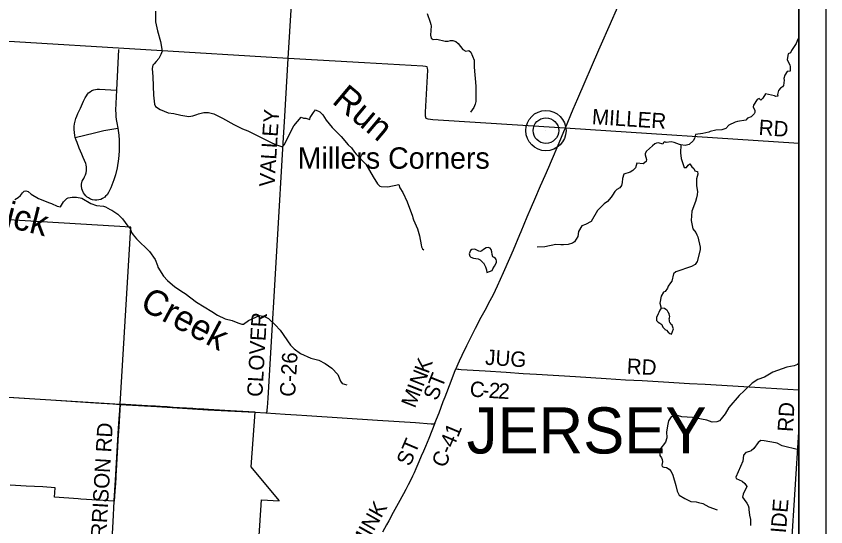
# Model space of a CAD drawing. Extents: x 0 to 91.3, y -0.7 to 22.
# Drawn here: x 6.008 to 9, y 18.226 to 20.113 of the extents above; entities that cross this region are included whole.
import ezdxf

# ---------------------------------------------------------------- set-up
doc = ezdxf.new("R2010")
doc.units = 0
for name, color, linetype in [('GM_X_Corporation', 7, 'Continuous'), ('GM_X_County_Road', 7, 'Continuous'), ('GM_X_County_Road_Text', 7, 'Continuous'), ('GM_X_Minor_Lake', 7, 'Continuous'), ('GM_X_Minor_River', 7, 'Continuous'), ('GM_X_Minor_River_Text', 7, 'Continuous'), ('GM_X_Township_Road', 7, 'Continuous'), ('GM_X_Township_Road_Text', 7, 'Continuous'), ('GM_X_Township_Text', 7, 'Continuous'), ('GM_X_Unincorporated', 7, 'Continuous'), ('GM_X_Unincorporated_Location', 7, 'Continuous'), ('GM_X_Unincorporated_Text', 7, 'Continuous'), ('SH_Data', 7, 'Continuous')]:
    doc.layers.add(name, color=color, linetype=linetype)

msp = doc.modelspace()

# ---------------------------------------------------------------- linework, layer by layer
at = {"layer": 'GM_X_Corporation'}
for points in [[(8.9, 14.1), (8.9, 20.9), (4.9555, 20.9), (4.9448, 20.7239), (4.9376, 20.6305), (4.9205, 20.3667), (4.8352, 18.7619), (4.834, 18.7568), (4.8336, 18.7529), (4.8277, 18.656), (4.8271, 18.6491), (4.8263, 18.646), (4.8251, 18.6439), (4.8242, 18.6326), (4.7833, 18.1361)], [(8.9, 15.2596), (8.9, 20.4953), (8.8785, 20.4965), (8.3956, 20.5276), (7.5521, 20.5793), (7.0477, 20.6033), (6.6637, 20.6293), (6.253, 20.6521), (5.6061, 20.6867), (4.9448, 20.7239), (4.9376, 20.6305), (4.9205, 20.3667), (4.8352, 18.7619), (4.834, 18.7568), (4.8336, 18.7529), (4.8277, 18.656), (4.8271, 18.6491), (4.8263, 18.646), (4.8251, 18.6439), (4.8242, 18.6326), (4.7833, 18.1361)], [(5.5451, 18.7322), (6.3918, 18.6787), (6.4311, 19.3332), (5.9167, 19.3643)], [(6.9007, 18.1177), (6.9141, 18.3252), (6.9792, 18.3213), (6.9793, 18.3233), (6.8762, 18.447), (6.8916, 18.6498), (6.7997, 18.6545), (6.7185, 18.6591), (6.6854, 18.6612), (6.6871, 18.6608), (6.6608, 18.6627), (6.6371, 18.6641), (6.636, 18.6642), (6.5876, 18.6671), (6.5653, 18.6685), (6.5405, 18.67), (6.5229, 18.6711), (6.4936, 18.6729), (6.4508, 18.6753), (6.3918, 18.6787), (6.3869, 18.5952), (6.384, 18.5468), (6.3822, 18.5174), (6.3812, 18.4997), (6.3785, 18.4551), (6.3761, 18.4138), (6.3757, 18.4077), (6.3744, 18.3859), (6.3727, 18.3576), (6.3705, 18.3205), (6.2473, 18.3276), (6.2373, 18.3287), (6.149, 18.3356), (6.1514, 18.3702), (6.1059, 18.3728), (6.045, 18.3762), (5.986, 18.3796)]]:
    msp.add_lwpolyline(points, dxfattribs=at)
at = {"layer": 'GM_X_County_Road'}
msp.add_line((6.8901, 18.6489), (6.93, 18.6467), dxfattribs=at)
for points in [[(6.93, 18.6467), (6.9336, 18.6494), (6.9353, 18.653), (6.936, 18.6574), (6.9365, 18.6665), (6.9388, 18.7016), (6.9771, 19.3495), (6.9908, 19.5807), (6.9947, 19.6438), (7.001, 19.743), (7.0134, 19.9559), (7.0324, 20.2772), (7.0426, 20.4438), (7.0492, 20.5571), (7.0503, 20.5744), (7.0503, 20.5854), (7.0499, 20.5936), (7.0491, 20.5984), (7.0479, 20.6028)], [(8.2333, 20.1542), (8.198, 20.0731), (8.1698, 20.009), (8.1602, 19.9873), (8.0825, 19.8073), (8.0656, 19.7677), (8.0368, 19.6987), (8.031, 19.6851), (8.0138, 19.6439), (7.9849, 19.5766), (7.975, 19.5536), (7.9615, 19.5234), (7.9448, 19.4851), (7.9229, 19.4348), (7.9111, 19.4066), (7.895, 19.3697), (7.8727, 19.3163), (7.8678, 19.3046), (7.8441, 19.2481), (7.8313, 19.2176), (7.8082, 19.1643), (7.7858, 19.1151), (7.7709, 19.0833), (7.7589, 19.0605), (7.7398, 19.025), (7.7255, 18.9987), (7.7042, 18.9582), (7.6912, 18.9336), (7.6718, 18.8944), (7.6545, 18.8587), (7.645, 18.8374), (7.6399, 18.8262), (7.6332, 18.8098)], [(7.5553, 18.6082), (7.5705, 18.6468), (7.5863, 18.6884), (7.5933, 18.7056), (7.6158, 18.7636), (7.628, 18.7971), (7.6332, 18.8098)], [(7.6332, 18.8098), (7.6403, 18.8083), (7.6437, 18.8079), (7.6526, 18.8072), (7.7415, 18.8018), (7.8187, 18.7968), (7.8814, 18.7928), (7.9313, 18.7898), (8.0749, 18.7817), (8.1888, 18.7738), (8.2592, 18.7694), (8.3207, 18.7658), (8.3998, 18.7613), (8.4963, 18.7559), (8.5542, 18.7525), (8.7373, 18.7412), (8.9, 18.7315)], [(5.5353, 18.731), (5.5363, 18.731), (5.5413, 18.7306), (5.6887, 18.7219), (5.882, 18.71), (5.98, 18.7044), (6.1355, 18.6949), (6.3006, 18.6844), (6.3651, 18.68), (6.3921, 18.6782)], [(6.3702, 18.3207), (6.3703, 18.3226), (6.3753, 18.3983), (6.3863, 18.5897), (6.3897, 18.6407), (6.3905, 18.6553), (6.3921, 18.6782)], [(6.3921, 18.6782), (6.5272, 18.6699), (6.7167, 18.6583), (6.8901, 18.6489)], [(6.93, 18.6467), (7.002, 18.6425), (7.0444, 18.6397), (7.0823, 18.6365), (7.3428, 18.6192), (7.4837, 18.6108), (7.5411, 18.6068), (7.545, 18.6062), (7.5486, 18.606), (7.5518, 18.6065), (7.5553, 18.6082)], [(7.5553, 18.6082), (7.533, 18.552), (7.5205, 18.5228), (7.5131, 18.5055), (7.5051, 18.4873), (7.496, 18.4662), (7.4848, 18.4401), (7.4781, 18.4254), (7.4725, 18.4133), (7.4648, 18.3964), (7.4567, 18.381), (7.4478, 18.364), (7.4393, 18.3481), (7.4192, 18.3114), (7.4011, 18.2784), (7.3847, 18.2477), (7.3765, 18.2324), (7.3618, 18.2063)], [(6.3746, 18.0328), (6.3737, 18.033), (6.3716, 18.0336), (6.3675, 18.0351), (6.3636, 18.0378), (6.3609, 18.0403), (6.3587, 18.0436), (6.3571, 18.0467), (6.3558, 18.0507), (6.3551, 18.055), (6.3547, 18.0604), (6.3553, 18.07), (6.3571, 18.0936), (6.3592, 18.1238), (6.3616, 18.17), (6.3636, 18.2011), (6.3664, 18.2435), (6.3702, 18.3207)]]:
    msp.add_lwpolyline(points, dxfattribs=at)
at = {"layer": 'GM_X_Minor_Lake'}
for points in [[(7.7244, 19.243), (7.718, 19.2438), (7.7028, 19.2514), (7.6922, 19.2511), (7.6869, 19.2474), (7.6822, 19.2349), (7.6845, 19.2258), (7.6882, 19.2219), (7.6977, 19.2185), (7.7151, 19.2165), (7.7231, 19.2119), (7.7336, 19.2016), (7.7355, 19.2008), (7.7419, 19.1867), (7.746, 19.175), (7.7456, 19.1742)], [(7.7456, 19.1742), (7.7478, 19.1651), (7.7664, 19.1729), (7.7699, 19.1786), (7.776, 19.1888), (7.7825, 19.202), (7.7829, 19.2085), (7.7818, 19.2134), (7.7796, 19.2172), (7.7743, 19.2207), (7.7694, 19.223), (7.7668, 19.2317), (7.7661, 19.242), (7.7635, 19.2503), (7.7597, 19.2549), (7.7525, 19.2583), (7.7445, 19.2561), (7.735, 19.2501), (7.7293, 19.2456), (7.7244, 19.243)], [(8.392, 19.0339), (8.3862, 19.0259), (8.3835, 19.0172), (8.3805, 19.0123), (8.3747, 18.9998), (8.3743, 18.9877), (8.3799, 18.9816), (8.3871, 18.9778), (8.3943, 18.9739), (8.3954, 18.9701), (8.3976, 18.9629), (8.4052, 18.9564), (8.4055, 18.9545), (8.4112, 18.9522), (8.418, 18.9446), (8.4237, 18.94), (8.4297, 18.9373)], [(8.4297, 18.9373), (8.4374, 18.9574), (8.4344, 18.9635), (8.4318, 18.9707), (8.4276, 18.9745), (8.4258, 18.9783), (8.4239, 18.9806), (8.4228, 18.9855), (8.422, 18.9889), (8.4213, 18.9939), (8.4221, 18.9984), (8.4232, 19.0026), (8.4225, 19.0052), (8.4207, 19.014), (8.4173, 19.0189), (8.4154, 19.0235), (8.412, 19.0269), (8.4082, 19.0292), (8.4037, 19.0319), (8.392, 19.0339)]]:
    msp.add_lwpolyline(points, dxfattribs=at)
at = {"layer": 'GM_X_Minor_River'}
for points in [[(6.523, 20.1312), (6.5228, 20.0918), (6.5302, 20.0584), (6.5413, 20.0193), (6.5479, 19.9836), (6.5429, 19.9707), (6.5345, 19.9567), (6.5257, 19.9458), (6.5181, 19.9371), (6.5132, 19.9318), (6.5101, 19.9193), (6.5129, 19.8882), (6.5148, 19.8207), (6.5192, 19.7881), (6.5233, 19.779), (6.5395, 19.7675), (6.569, 19.756), (6.5906, 19.7532), (6.6168, 19.747), (6.6459, 19.7426), (6.6611, 19.7444), (6.6759, 19.75), (6.682, 19.7523), (6.701, 19.7567), (6.718, 19.7574), (6.7385, 19.7523), (6.7702, 19.7362), (6.8126, 19.7124), (6.8443, 19.6967), (6.8636, 19.6894), (6.8833, 19.6787), (6.9472, 19.6468), (6.9661, 19.6387), (6.9918, 19.6302), (6.9983, 19.637), (7.0343, 19.7073), (7.0614, 19.7398), (7.0697, 19.7359), (7.0785, 19.7359), (7.0925, 19.7316), (7.0948, 19.7384), (7.1063, 19.7566), (7.1146, 19.7664), (7.1298, 19.7598), (7.1411, 19.7484), (7.1535, 19.729), (7.1757, 19.7016), (7.2085, 19.668), (7.2345, 19.6371), (7.2469, 19.6257), (7.2586, 19.6101), (7.2642, 19.6032), (7.2997, 19.5659), (7.3271, 19.5191), (7.3429, 19.4932), (7.3519, 19.4844), (7.3568, 19.4829), (7.3811, 19.4827), (7.4217, 19.4904), (7.4262, 19.4779), (7.4371, 19.4608), (7.4532, 19.4262), (7.4722, 19.3737), (7.4741, 19.3673), (7.4759, 19.3597), (7.4905, 19.327), (7.4987, 19.3016), (7.5042, 19.2678), (7.5057, 19.2598), (7.5095, 19.253), (7.5144, 19.2499)], [(7.5265, 20.1226), (7.5377, 20.0903), (7.5399, 20.0823), (7.5414, 20.0766), (7.5393, 20.0425), (7.5415, 20.0311), (7.5494, 20.0269), (7.5627, 20.0283), (7.593, 20.0202), (7.6044, 20.0209), (7.6127, 20.0231), (7.6211, 20.0231), (7.6324, 20.0196), (7.6415, 20.0123), (7.6584, 19.9902), (7.6698, 19.9837), (7.6808, 19.9856), (7.6875, 19.9794), (7.7003, 19.9498), (7.7006, 19.9437), (7.7001, 19.924), (7.7066, 19.8546), (7.7062, 19.7974), (7.7047, 19.7879), (7.6993, 19.775), (7.6867, 19.7584)], [(8.9, 20.032), (8.8968, 20.0283), (8.8941, 20.0219), (8.8899, 20.0117), (8.8731, 19.9864), (8.8696, 19.9773), (8.8609, 19.9732), (8.8577, 19.9523), (8.8675, 19.9314), (8.8686, 19.9265), (8.8681, 19.9098), (8.8567, 19.9087), (8.8491, 19.8948), (8.8448, 19.883), (8.8463, 19.8762), (8.8432, 19.8561), (8.8401, 19.8512), (8.8329, 19.8471), (8.8253, 19.8388), (8.8214, 19.8236), (8.8221, 19.8172), (8.8153, 19.8157), (8.8104, 19.8184), (8.7767, 19.8258), (8.7667, 19.81), (8.7598, 19.8024), (8.7531, 19.8081), (8.7466, 19.8055), (8.7328, 19.7836), (8.7313, 19.7783), (8.738, 19.7642), (8.7376, 19.757), (8.7349, 19.7518), (8.7242, 19.7408), (8.7106, 19.736), (8.7045, 19.7288), (8.6733, 19.7237), (8.6654, 19.7215), (8.6418, 19.7095), (8.6307, 19.6974), (8.6155, 19.6933), (8.5932, 19.692)], [(8.5932, 19.692), (8.573, 19.6871), (8.5677, 19.6845), (8.5461, 19.6793), (8.5184, 19.6761), (8.5149, 19.6613), (8.5099, 19.6519), (8.4951, 19.6387), (8.4799, 19.6346), (8.4647, 19.6374), (8.4594, 19.6382), (8.4401, 19.6462), (8.4284, 19.6482), (8.4106, 19.6457), (8.4053, 19.648), (8.4003, 19.6465), (8.398, 19.64), (8.3817, 19.6443), (8.3745, 19.6432), (8.3677, 19.6406), (8.3589, 19.6342), (8.3368, 19.6135), (8.3326, 19.6056), (8.3322, 19.5999), (8.3378, 19.5835), (8.3362, 19.576), (8.3244, 19.5673), (8.3013, 19.5694), (8.2963, 19.5523), (8.2868, 19.5429), (8.2769, 19.5358), (8.2541, 19.5294), (8.2483, 19.5124), (8.2478, 19.4984), (8.2444, 19.487), (8.2386, 19.4784), (8.2272, 19.4724), (8.22, 19.4652), (8.2112, 19.4512), (8.2066, 19.444), (8.1936, 19.4282), (8.1814, 19.4192), (8.1559, 19.3947), (8.1325, 19.3543), (8.1124, 19.343), (8.0987, 19.3382), (8.0865, 19.3174), (8.0833, 19.2981), (8.0715, 19.2788), (8.0639, 19.2743), (8.0483, 19.2691), (8.0308, 19.268), (8.021, 19.2681), (8.0024, 19.2694), (7.9614, 19.2609), (7.933, 19.2592)], [(8.4638, 19.6375), (8.463, 19.6078), (8.4656, 19.5866), (8.476, 19.5535), (8.4855, 19.5538), (8.4912, 19.5621), (8.4973, 19.5667), (8.5044, 19.5556), (8.5124, 19.5495), (8.5161, 19.5415), (8.5263, 19.5384), (8.5274, 19.5293), (8.5216, 19.5119), (8.5227, 19.496), (8.5215, 19.4861), (8.5252, 19.4645), (8.5243, 19.4524), (8.5216, 19.4418), (8.5185, 19.4278), (8.5051, 19.3926), (8.5022, 19.3581), (8.5088, 19.3266), (8.5198, 19.3136), (8.5231, 19.3053), (8.5273, 19.2973), (8.5354, 19.2597), (8.5357, 19.2495), (8.5249, 19.2056), (8.5172, 19.1954), (8.5035, 19.1875), (8.4462, 19.1681), (8.4374, 19.161), (8.4308, 19.133), (8.4255, 19.1277), (8.4174, 19.1152), (8.4151, 19.108), (8.4063, 19.0956), (8.4002, 19.0929), (8.3911, 19.0782), (8.3871, 19.0527), (8.392, 19.0339)], [(6.0031, 19.4356), (6.0153, 19.4431), (6.0244, 19.4502), (6.0317, 19.4604), (6.0378, 19.4657), (6.0439, 19.4679), (6.0518, 19.4648), (6.0635, 19.4549), (6.0907, 19.4388), (6.1312, 19.423), (6.138, 19.42), (6.1596, 19.4104), (6.1721, 19.4088), (6.1831, 19.4262), (6.195, 19.439), (6.1999, 19.4416), (6.2143, 19.4442), (6.2303, 19.4441), (6.2507, 19.4398), (6.284, 19.421), (6.3044, 19.4133), (6.3305, 19.4109), (6.3377, 19.4086), (6.3555, 19.399), (6.3612, 19.3955), (6.3831, 19.3817), (6.4012, 19.3638), (6.42, 19.3372), (6.429, 19.3276), (6.4339, 19.3128), (6.4399, 19.3052), (6.4519, 19.2896), (6.5006, 19.2427), (6.5209, 19.2141), (6.5295, 19.1913), (6.5313, 19.1852), (6.5528, 19.1514), (6.5671, 19.1361), (6.5939, 19.1128), (6.6264, 19.0918), (6.632, 19.0876), (6.6747, 19.0555), (6.731, 19.0218), (6.7514, 19.0084), (6.7797, 18.9942), (6.8066, 18.988), (6.8267, 18.9799), (6.8418, 18.9749), (6.8482, 18.9748), (6.8665, 18.988), (6.9076, 19.0063), (6.9257, 19.0032), (6.9409, 18.9951), (6.965, 18.9726), (6.9835, 18.9528), (7.0218, 18.8965), (7.0305, 18.8881), (7.0354, 18.8835), (7.0592, 18.8667), (7.097, 18.8494), (7.1269, 18.8412), (7.1496, 18.829), (7.1749, 18.8118), (7.1971, 18.7889), (7.2068, 18.7638), (7.2125, 18.7547), (7.2295, 18.7508)], [(8.9, 18.8288), (8.895, 18.8253), (8.8825, 18.8205), (8.8555, 18.8153), (8.8046, 18.7978)], [(8.8046, 18.7978), (8.7738, 18.7791), (8.7484, 18.7697), (8.7274, 18.7562), (8.6981, 18.7279), (8.6802, 18.711), (8.642, 18.6669), (8.6275, 18.6434), (8.6133, 18.6246), (8.6069, 18.6174), (8.5974, 18.6133), (8.5795, 18.6126), (8.5606, 18.6196), (8.5148, 18.629), (8.5072, 18.6301), (8.4682, 18.6323), (8.4557, 18.6358), (8.4401, 18.6358), (8.4288, 18.6317), (8.4188, 18.617), (8.4161, 18.6049), (8.4118, 18.5761), (8.4128, 18.5549), (8.407, 18.5382), (8.3868, 18.5118), (8.3856, 18.5035), (8.3862, 18.4891), (8.3923, 18.4811), (8.3953, 18.4742), (8.3967, 18.4663), (8.394, 18.4538), (8.3951, 18.4488), (8.4008, 18.4461), (8.411, 18.4446), (8.4212, 18.4384), (8.4288, 18.43), (8.4344, 18.4167), (8.4455, 18.3788), (8.4507, 18.3575), (8.4586, 18.343), (8.4786, 18.33), (8.5017, 18.3193), (8.5214, 18.3176), (8.5297, 18.3161), (8.546, 18.3114), (8.5675, 18.2999), (8.5989, 18.288)], [(8.9, 18.5105), (8.8989, 18.5102), (8.8387, 18.5246), (8.8206, 18.5342), (8.8142, 18.5365), (8.7721, 18.544), (8.7604, 18.5448), (8.7505, 18.5373), (8.7337, 18.5147), (8.7238, 18.5068), (8.7181, 18.5045), (8.704, 18.5), (8.6952, 18.4906), (8.6928, 18.4679), (8.6679, 18.4089), (8.6686, 18.404), (8.6913, 18.3943), (8.7007, 18.3859), (8.7086, 18.3749), (8.6944, 18.3458), (8.6925, 18.3356), (8.6977, 18.3261), (8.7079, 18.3131), (8.7128, 18.3044), (8.7154, 18.2956), (8.7153, 18.2899), (8.7179, 18.2683), (8.722, 18.2527), (8.7222, 18.2307)]]:
    msp.add_lwpolyline(points, dxfattribs=at)
at = {"layer": 'GM_X_Township_Road'}
for points in [[(8.9, 19.6421), (8.0368, 19.6987), (7.548, 19.73), (7.5299, 19.732), (7.5234, 19.7353), (7.5204, 19.743), (7.5209, 19.758), (7.5287, 19.9131), (7.5284, 19.9207), (7.5264, 19.9252), (7.5209, 19.9272), (7.5111, 19.9282), (7.2951, 19.9402), (7.0134, 19.9559), (5.4342, 20.0523)], [(6.3863, 19.9895), (6.3788, 19.84), (6.3753, 19.7657), (6.3756, 19.7517), (6.3758, 19.742), (6.377, 19.7313), (6.3792, 19.7183), (6.3834, 19.6987), (6.387, 19.6734), (6.3885, 19.655), (6.389, 19.6336), (6.3886, 19.6144), (6.3861, 19.5853), (6.3813, 19.5527), (6.375, 19.5262), (6.3693, 19.5082), (6.3577, 19.4786), (6.3492, 19.4615), (6.3437, 19.4524), (6.3385, 19.4471), (6.335, 19.4442), (6.3263, 19.4385), (6.3201, 19.4356), (6.3131, 19.4338), (6.3059, 19.4328), (6.2983, 19.433), (6.2903, 19.4341), (6.2826, 19.4366), (6.2749, 19.441), (6.2701, 19.4441), (6.2647, 19.4488), (6.2599, 19.4546), (6.2567, 19.4594), (6.2526, 19.4681), (6.2502, 19.4751), (6.2494, 19.4853), (6.2498, 19.4925), (6.2507, 19.498), (6.2521, 19.503), (6.2548, 19.5095), (6.2573, 19.5135), (6.2609, 19.5196), (6.2644, 19.5268), (6.2656, 19.53), (6.2664, 19.5335), (6.2674, 19.5426), (6.2675, 19.5481), (6.2673, 19.5544), (6.2659, 19.5633), (6.2647, 19.5685), (6.2604, 19.5794), (6.256, 19.5906), (6.2504, 19.6035), (6.2412, 19.6253), (6.2328, 19.6459), (6.2296, 19.6544), (6.2263, 19.6651), (6.225, 19.6719), (6.2232, 19.6831), (6.2226, 19.6936), (6.2224, 19.7055), (6.2237, 19.7149), (6.2254, 19.7252), (6.2283, 19.7351), (6.2314, 19.7439), (6.2355, 19.7529), (6.2393, 19.7604), (6.2454, 19.7731), (6.2566, 19.7989), (6.2623, 19.8107), (6.2672, 19.8189), (6.2715, 19.8247), (6.2757, 19.8292), (6.281, 19.8336), (6.2879, 19.838), (6.2944, 19.8403), (6.3008, 19.8421), (6.3077, 19.8434), (6.3161, 19.8436), (6.3788, 19.84)], [(6.2263, 19.6651), (6.2977, 19.6823), (6.3315, 19.6898), (6.3834, 19.6987)], [(8.8439, 17.5728), (8.854, 17.7851), (8.847, 17.875), (8.8729, 18.1514), (8.9, 18.5752)]]:
    msp.add_lwpolyline(points, dxfattribs=at)
at = {"layer": 'GM_X_Unincorporated'}
for radius in [0.0744, 0.0472]:
    msp.add_circle((7.9656, 19.6899), radius, dxfattribs=at)
at = {"layer": 'GM_X_Unincorporated_Location'}
msp.add_line((7.9656, 19.6899), (7.9656, 19.6899), dxfattribs=at)
at = {"layer": 'SH_Data'}
for p, q in [((9, 21), (9, 14)), ((8.9, 20.9), (8.9, 14.1))]:
    msp.add_line(p, q, dxfattribs=at)

# ---------------------------------------------------------------- texts
at = {"layer": 'GM_X_County_Road_Text'}
for s, height, rotation, p in [('VALLEY', 0.05682, 86.4127, (6.9624, 19.4806)), ('CLOVER', 0.05682, 86.7342, (6.9174, 18.7046)), ('JUG', 0.05682, 356.2828, (7.7398, 18.8248)), ('C-26', 0.05682, 86.5738, (7.0383, 18.7049)), ('K', 0.0568, 70.2745, (7.5313, 18.7888)), ('RD', 0.05682, 357.0388, (8.2634, 18.7915)), ('N', 0.0568, 68.4983, (7.5123, 18.7405)), ('ST', 0.05682, 68.4004, (7.5632, 18.6886)), ('C', 0.0568, 355.9414, (7.6827, 18.7074)), ('M', 0.0568, 68.4991, (7.4812, 18.6615)), ('I', 0.0568, 68.5064, (7.5038, 18.7188)), ('2', 0.0568, 356.0884, (7.7527, 18.7024)), ('2', 0.0568, 356.7709, (7.7884, 18.7)), ('-', 0.0568, 355.9771, (7.7293, 18.7041)), ('HARRISON RD', 0.056818, 86.6573, (6.3341, 18.0781)), ('C-41', 0.05682, 67.2488, (7.5931, 18.4406)), ('ST', 0.05682, 66.9486, (7.4633, 18.4463)), ('MINK', 0.05682, 60.6284, (7.2881, 18.1334))]:
    msp.add_text(s, height=height, rotation=rotation, dxfattribs=at).set_placement(p)
at = {"layer": 'GM_X_Minor_River_Text'}
for s, rotation, p in [('Run', 320.0023, (7.1713, 19.7944)), ('Blacklick', 346.0026, (5.6354, 19.418)), ('Creek', 332.0023, (6.4605, 19.033))]:
    msp.add_text(s, height=0.0947, rotation=rotation, dxfattribs=at).set_placement(p)
at = {"layer": 'GM_X_Township_Road_Text'}
for s, rotation, p in [('MILLER', 356.2973, (8.1344, 19.7141)), ('RD', 356.0531, (8.7504, 19.6741)), ('RD', 86.5421, (8.8782, 18.5753)), ('BURNSIDE', 85.3612, (8.8308, 17.9355))]:
    msp.add_text(s, height=0.05682, rotation=rotation, dxfattribs=at).set_placement(p)
at = {"layer": 'GM_X_Township_Text'}
msp.add_text('JERSEY', height=0.17045, rotation=0, dxfattribs=at).set_placement((7.6727, 18.4966))
at = {"layer": 'GM_X_Unincorporated_Text'}
msp.add_text('Millers Corners', height=0.078977, rotation=0, dxfattribs=at).set_placement((7.048, 19.5491))

doc.saveas('drawing.dxf')
